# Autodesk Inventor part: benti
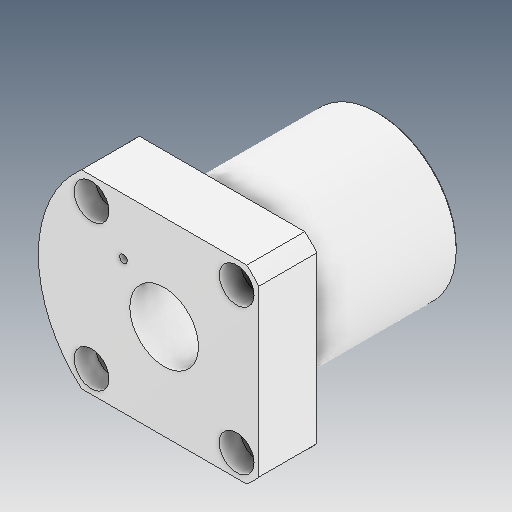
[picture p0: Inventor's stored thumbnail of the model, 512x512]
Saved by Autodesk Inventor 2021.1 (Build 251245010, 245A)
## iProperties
Created: 2021-05
Part Number: benti
Material: Ogólny
Document SubType Name: Modeling
Designer: user
Density: 1 g/cm^3
Appearance: Domyślna
Author: user
Revision Number: ÈÎºÎ
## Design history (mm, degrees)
feature "Í¹Ì¨-À­Éì2"
node "Bryła1"
